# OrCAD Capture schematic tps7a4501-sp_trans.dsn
size B
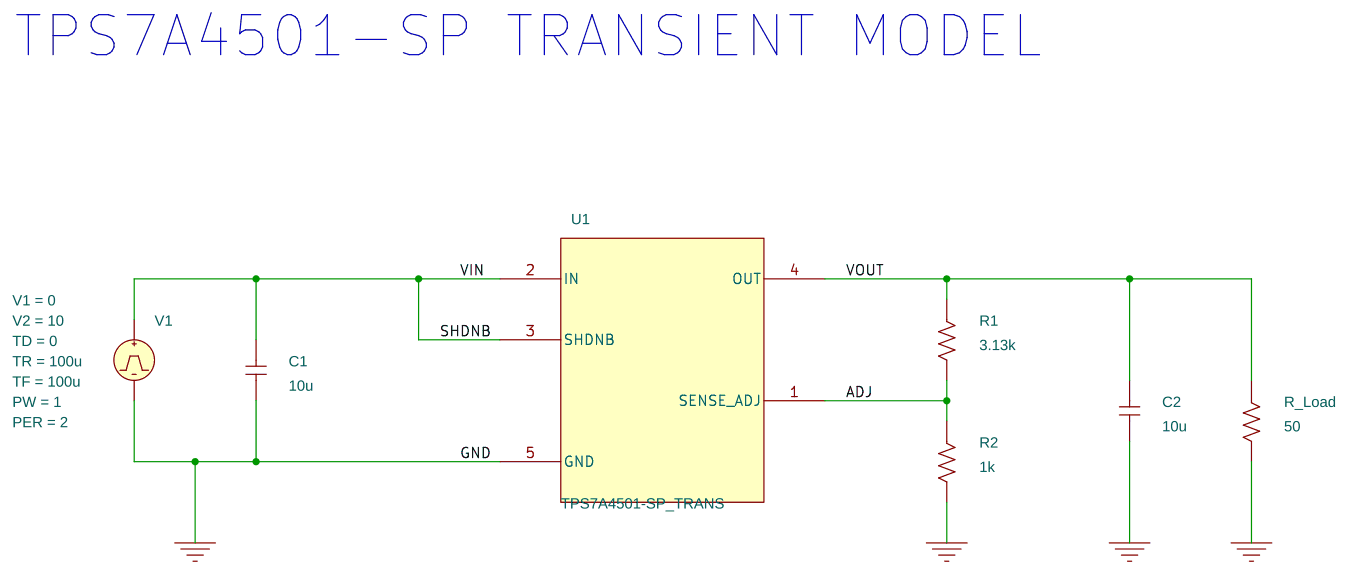
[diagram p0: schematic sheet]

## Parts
C1  10u  [RAD/CK05]
C2  10u  [RAD/CK05]
R1  3.13k  [AX/RC05]
R2  1k  [AX/RC05]
R_Load  50  [AX/RC05]
U1  TPS7A4501-SP_TRANS
V1  VPULSE

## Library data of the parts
C1 C2 = C
R1 R2 R_Load = R
U1 = TPS7A4501-SP_TRANS_1: PSpiceTemplate: X^@REFDES  %SENSE_ADJ %IN %SHDNB %OUT %GND @MODEL
V1 = VPULSE: PER: 2; PW: 1; TD: 0; TF: 100u; TR: 100u; V1: 0; V2: 10

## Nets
0: C1.1 C2.1 R2.2 R_Load.2 U1.5(GND) V1.2(-)
ADJ: R1.2 R2.1 U1.1(SENSE_ADJ)
SHDNB: C1.2 U1.2(IN) U1.3(SHDNB) V1.1(+)
VOUT: C2.2 R1.1 R_Load.1 U1.4(OUT)

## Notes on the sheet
- TPS7A4501-SP TRANSIENT MODEL
